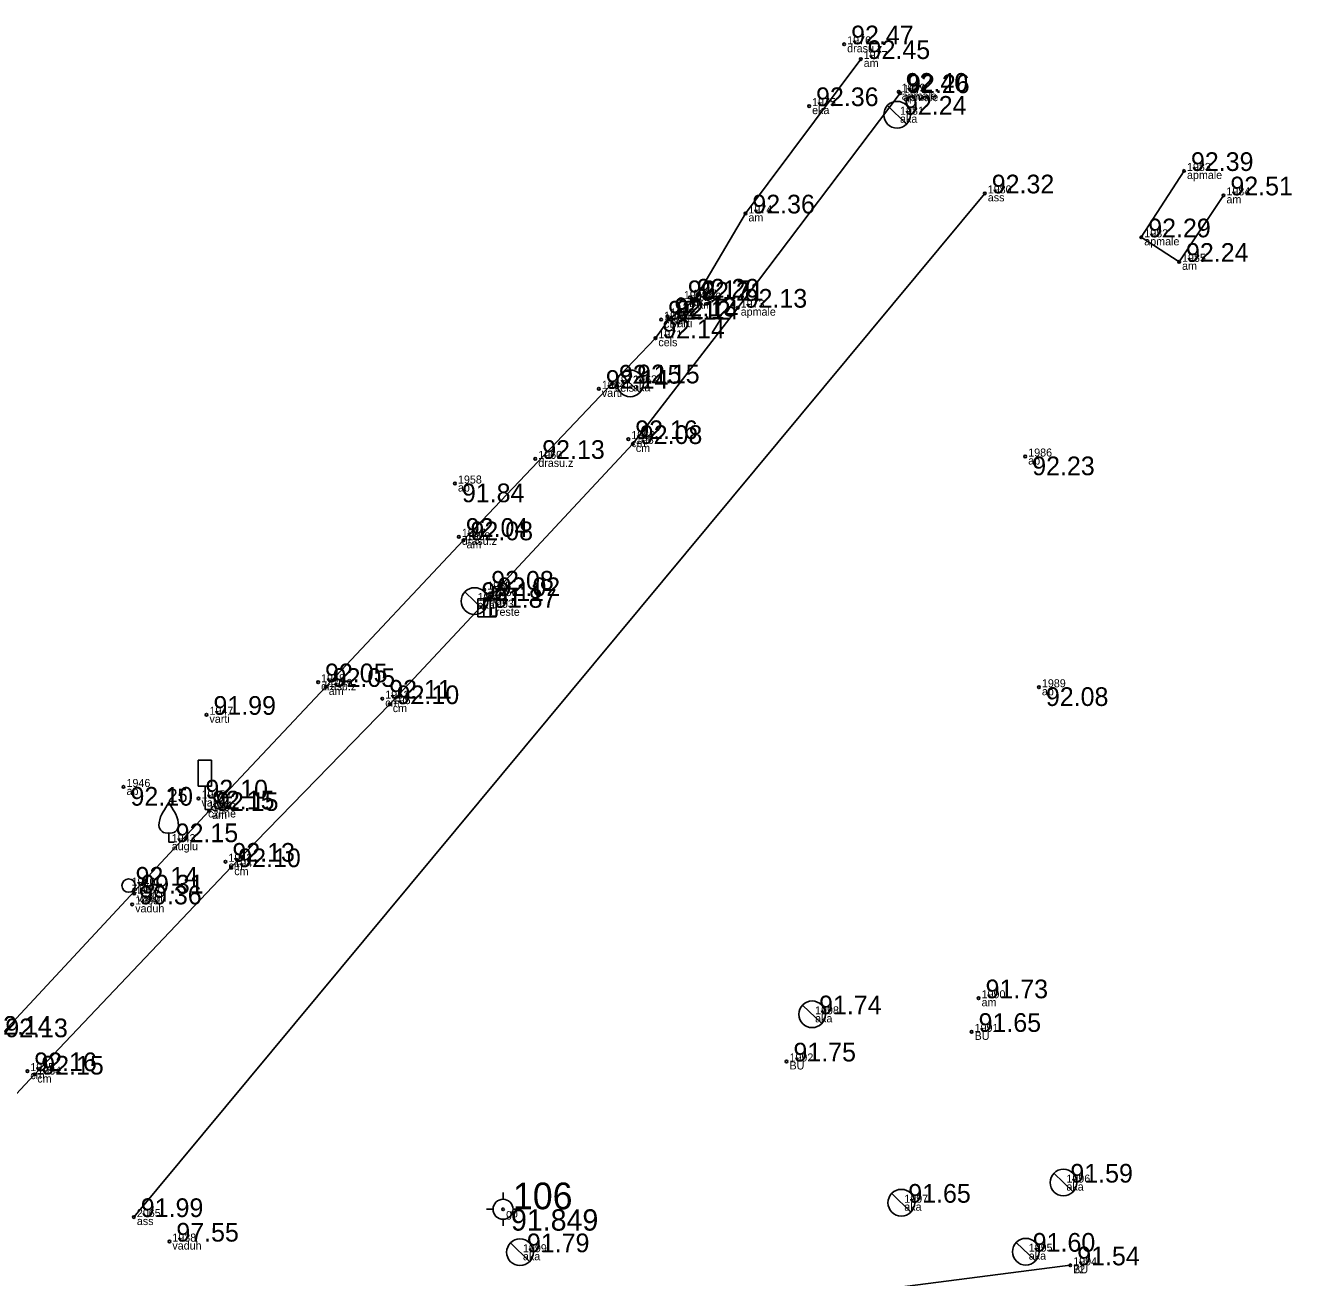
# Model space of a CAD drawing. Extents: x 614911 to 615803, y 262110 to 264311.
# Drawn here: x 615755.92 to 615803.38, y 263539.24 to 263586.14 of the extents above; entities that cross this region are included whole.
import ezdxf

# ---------------------------------------------------------------- set-up
doc = ezdxf.new("R2010")
doc.units = 0
for name, color, linetype in [('Level 1', 7, 'Continuous'), ('Level 12', 7, 'Continuous'), ('Level 16', 7, 'Continuous'), ('Level 18', 7, 'Continuous'), ('Level 19', 7, 'Continuous'), ('Level 37', 7, 'Continuous'), ('Level 48', 7, 'Continuous'), ('Level 53', 7, 'Continuous'), ('Level 54', 7, 'Continuous'), ('Level 57', 7, 'Continuous'), ('Level 58', 7, 'Continuous')]:
    doc.layers.add(name, color=color, linetype=linetype)

msp = doc.modelspace()

# ---------------------------------------------------------------- linework, layer by layer
at = {"layer": 'Level 1'}
for p, q in [((615761.297, 263555.9), (615761.297, 263555.548)), ((615761.297, 263555.548), (615761.497, 263555.548))]:
    msp.add_line(p, q, dxfattribs=at)
for centre, radius, start, end in [((615773.922, 263549.152), 14.88, 148.4844, 149.9901), ((615760.88, 263557.186), 0.439, 324.3837, 341.712), ((615761.714, 263557.186), 0.439, 198.288, 215.6163), ((615748.672, 263549.152), 14.88, 30.0099, 31.5156), ((615761.821, 263556.173), 0.89, 151.757, 179.9138), ((615760.773, 263556.173), 0.89, 0.0862, 28.243), ((615761.221, 263556.179), 0.29, 181.0782, 285.2823), ((615761.373, 263556.179), 0.29, 254.7177, 358.9218)]:
    msp.add_arc(centre, radius, start, end, dxfattribs=at)
at = {"layer": 'Level 12'}
for p, q in [((615788.232, 263583.144), (615788.95, 263582.448)), ((615778.23, 263573.082), (615778.948, 263572.386)), ((615772.399, 263564.928), (615773.117, 263564.232)), ((615785.049, 263549.448), (615785.767, 263548.752)), ((615794.467, 263543.145), (615795.185, 263542.449)), ((615788.392, 263542.391), (615789.11, 263541.695)), ((615774.101, 263540.536), (615774.819, 263539.84)), ((615793.056, 263540.556), (615793.774, 263539.86))]:
    msp.add_line(p, q, dxfattribs=at)
for centre in [(615788.591, 263582.796), (615778.589, 263572.734), (615772.758, 263564.58), (615785.408, 263549.1), (615794.826, 263542.797), (615788.751, 263542.043), (615774.46, 263540.188), (615793.415, 263540.208)]:
    msp.add_circle(centre, 0.5, dxfattribs=at)
at = {"layer": 'Level 16'}
for p, q in [((615762.904, 263558.62), (615762.404, 263558.62)), ((615762.404, 263557.651), (615762.404, 263558.62)), ((615762.904, 263557.651), (615762.904, 263558.62)), ((615762.904, 263557.651), (615762.404, 263557.651)), ((615762.658, 263557.651), (615762.658, 263556.773)), ((615762.658, 263556.773), (615762.973, 263556.773))]:
    msp.add_line(p, q, dxfattribs=at)
at = {"layer": 'Level 18'}
msp.add_circle((615759.794, 263553.919), 0.25, dxfattribs=at)
at = {"layer": 'Level 19'}
for p, q in [((615773.825, 263542.172), (615773.825, 263542.422)), ((615773.2, 263541.797), (615773.45, 263541.797)), ((615774.2, 263541.797), (615774.45, 263541.797)), ((615773.825, 263541.172), (615773.825, 263541.422))]:
    msp.add_line(p, q, dxfattribs=at)
for radius in [0.375, 0.05]:
    msp.add_circle((615773.825, 263541.797), radius, dxfattribs=at)
at = {"layer": 'Level 37'}
for points in [[(615787.229, 263584.883), (615782.908, 263579.099), (615780.991, 263575.833), (615780.048, 263575.138), (615779.534, 263574.424), (615777.908, 263572.723), (615772.346, 263566.856), (615767.18, 263561.364), (615762.809, 263556.719), (615754.912, 263548.241), (615748.93, 263542.698)], [(615748.501, 263540.3), (615752.458, 263542.769), (615756.26, 263546.844), (615763.642, 263554.612), (615769.579, 263560.719), (615773.362, 263564.765), (615778.69, 263570.463), (615782.62, 263575.569), (615788.708, 263583.605)], [(615799.345, 263580.69), (615797.744, 263578.204), (615799.159, 263577.287), (615800.822, 263579.776)], [(615759.991, 263541.506), (615791.879, 263579.85)], [(615636.517, 263431.183), (615636.486, 263438.842), (615637.482, 263455.724), (615637.88, 263461.317), (615641.087, 263475.093), (615646.009, 263486.103), (615652.8, 263496.474), (615655.118, 263496.071), (615654.594, 263498.729), (615665.688, 263509.023), (615675.1, 263515.158), (615678.975, 263516.543), (615699.763, 263520.908), (615714.967, 263523.826), (615751.888, 263531.363), (615772.751, 263536.064), (615784.721, 263538.367), (615795.082, 263539.698)]]:
    msp.add_lwpolyline(points, dxfattribs=at)
at = {"layer": 'Level 48'}
for p, q in [((615773.111, 263564.666), (615773.111, 263563.991)), ((615773.336, 263564.666), (615773.336, 263563.991))]:
    msp.add_line(p, q, dxfattribs=at)
msp.add_lwpolyline([(615772.886, 263564.666), (615773.561, 263564.666), (615773.561, 263563.991), (615772.886, 263563.991)], close=True, dxfattribs=at)
at = {"layer": 'Level 57'}
for centre in [(615786.61, 263585.434), (615787.229, 263584.883), (615788.652, 263583.657), (615788.708, 263583.605), (615785.295, 263583.119), (615799.345, 263580.69), (615791.879, 263579.85), (615800.822, 263579.776), (615782.908, 263579.099), (615797.744, 263578.204), (615799.159, 263577.287), (615780.488, 263575.889), (615780.826, 263575.948), (615780.991, 263575.833), (615779.749, 263575.121), (615779.989, 263575.241), (615780.048, 263575.138), (615782.62, 263575.569), (615779.534, 263574.424), (615777.416, 263572.529), (615777.908, 263572.723), (615778.52, 263570.646), (615778.69, 263570.463), (615775.034, 263569.905), (615793.395, 263569.993), (615772.024, 263568.982), (615772.169, 263566.985), (615772.346, 263566.856), (615773.123, 263565.006), (615773.362, 263564.765), (615766.894, 263561.538), (615767.18, 263561.364), (615793.908, 263561.35), (615769.299, 263560.923), (615769.579, 263560.719), (615762.712, 263560.319), (615759.603, 263557.615), (615762.412, 263557.185), (615762.809, 263556.719), (615763.423, 263554.816), (615763.642, 263554.612), (615760.001, 263553.625), (615759.928, 263553.218), (615791.647, 263549.701), (615791.386, 263548.442), (615784.448, 263547.334), (615755.998, 263546.971), (615756.26, 263546.844), (615759.991, 263541.506), (615761.321, 263540.587), (615795.082, 263539.698)]:
    msp.add_circle(centre, 0.05, dxfattribs=at)
at = {"layer": 'Level 58'}
for centre in [(615786.61, 263585.434), (615787.229, 263584.883), (615788.652, 263583.657), (615788.708, 263583.605), (615785.295, 263583.119), (615799.345, 263580.69), (615791.879, 263579.85), (615800.822, 263579.776), (615782.908, 263579.099), (615797.744, 263578.204), (615799.159, 263577.287), (615780.488, 263575.889), (615780.826, 263575.948), (615780.991, 263575.833), (615779.749, 263575.121), (615779.989, 263575.241), (615780.048, 263575.138), (615782.62, 263575.569), (615779.534, 263574.424), (615777.416, 263572.529), (615777.908, 263572.723), (615778.52, 263570.646), (615778.69, 263570.463), (615775.034, 263569.905), (615793.395, 263569.993), (615772.024, 263568.982), (615772.169, 263566.985), (615772.346, 263566.856), (615773.123, 263565.006), (615773.362, 263564.765), (615766.894, 263561.538), (615767.18, 263561.364), (615793.908, 263561.35), (615769.299, 263560.923), (615769.579, 263560.719), (615762.712, 263560.319), (615759.603, 263557.615), (615762.412, 263557.185), (615762.809, 263556.719), (615763.423, 263554.816), (615763.642, 263554.612), (615760.001, 263553.625), (615759.928, 263553.218), (615791.647, 263549.701), (615791.386, 263548.442), (615784.448, 263547.334), (615755.998, 263546.971), (615756.26, 263546.844), (615759.991, 263541.506), (615761.321, 263540.587), (615795.082, 263539.698)]:
    msp.add_circle(centre, 0.05, dxfattribs=at)

# ---------------------------------------------------------------- texts
at = {"layer": 'Level 1'}
msp.add_text(' 25', height=0.5, dxfattribs=at).set_placement((615761.072, 263557.048))
at = {"layer": 'Level 19'}
for s, height, p in [(' 106', 1, (615773.825, 263541.797)), (' 91.849', 0.8, (615773.825, 263540.997))]:
    msp.add_text(s, height=height, dxfattribs=at).set_placement(p)
at = {"layer": 'Level 48'}
msp.add_text(' 91.87', height=0.7, dxfattribs=at).set_placement((615773.224, 263564.328))
at = {"layer": 'Level 53'}
for s, p in [(' drasu.z', (615786.61, 263585.134)), (' am', (615787.229, 263584.583)), (' apmale', (615788.652, 263583.357)), (' apmale', (615788.708, 263583.305)), (' eka', (615785.295, 263582.819)), (' aka', (615788.591, 263582.496)), (' apmale', (615799.345, 263580.39)), (' ass', (615791.879, 263579.55)), (' am', (615800.822, 263579.476)), (' am', (615782.908, 263578.799)), (' apmale', (615797.744, 263577.904)), (' am', (615799.159, 263576.987)), (' cBr', (615780.488, 263575.589)), (' eka', (615780.826, 263575.648)), (' am', (615780.991, 263575.533)), (' cBr', (615779.989, 263574.941)), (' apmale', (615782.62, 263575.269)), (' cBr', (615779.749, 263574.821)), (' varti', (615780.048, 263574.838)), (' cels', (615779.534, 263574.124)), (' varti', (615777.416, 263572.229)), (' cels', (615777.908, 263572.423)), (' aka', (615778.589, 263572.434)), (' cm', (615778.52, 263570.346)), (' cm', (615778.69, 263570.163)), (' drasu.z', (615775.034, 263569.605)), (' ap', (615793.395, 263569.693)), (' ap', (615772.024, 263568.682)), (' drasu.z', (615772.169, 263566.685)), (' am', (615772.346, 263566.556)), (' cm', (615773.123, 263564.706)), (' aka', (615772.758, 263564.28)), (' Lreste', (615773.224, 263564.028)), (' cm', (615773.362, 263564.465)), (' drasu.z', (615766.894, 263561.238)), (' am', (615767.18, 263561.064)), (' ap', (615793.908, 263561.05)), (' cm', (615769.299, 263560.623)), (' cm', (615769.579, 263560.419)), (' varti', (615762.712, 263560.019)), (' ap', (615759.603, 263557.315)), (' varti', (615762.412, 263556.885)), (' czime', (615762.658, 263556.473)), (' am', (615762.809, 263556.419)), (' auglu', (615761.297, 263555.248)), (' cm', (615763.423, 263554.516)), (' cm', (615763.642, 263554.312)), (' elst', (615759.794, 263553.619)), (' vaduh', (615760.001, 263553.325)), (' vaduh', (615759.928, 263552.918)), (' am', (615791.647, 263549.401)), (' aka', (615785.408, 263548.8)), (' BU', (615791.386, 263548.142)), (' BU', (615784.448, 263547.034)), (' cm', (615755.998, 263546.671)), (' cm', (615756.26, 263546.544)), (' aka', (615794.826, 263542.497)), (' aka', (615788.751, 263541.743)), (' gp', (615773.825, 263541.497)), (' ass', (615759.991, 263541.206)), (' vaduh', (615761.321, 263540.287)), (' aka', (615774.46, 263539.888)), (' aka', (615793.415, 263539.908)), (' 72', (615795.082, 263539.398)), (' BU', (615795.082, 263539.398))]:
    msp.add_text(s, height=0.3, dxfattribs=at).set_placement(p)
at = {"layer": 'Level 54'}
for s, p in [(' 1976', (615786.61, 263585.434)), (' 1977', (615787.229, 263584.883)), (' 1979', (615788.652, 263583.657)), (' 1978', (615788.708, 263583.605)), (' 1975', (615785.295, 263583.119)), (' 1981', (615788.591, 263582.796)), (' 1983', (615799.345, 263580.69)), (' 1980', (615791.879, 263579.85)), (' 1984', (615800.822, 263579.776)), (' 1974', (615782.908, 263579.099)), (' 1982', (615797.744, 263578.204)), (' 1985', (615799.159, 263577.287)), (' 1968', (615780.488, 263575.889)), (' 1967', (615780.826, 263575.948)), (' 1966', (615780.991, 263575.833)), (' 1973', (615782.62, 263575.569)), (' 1970', (615779.749, 263575.121)), (' 1969', (615779.989, 263575.241)), (' 1965', (615780.048, 263575.138)), (' 1971', (615779.534, 263574.424)), (' 1964', (615777.416, 263572.529)), (' 1972', (615777.908, 263572.723)), (' 1963', (615778.589, 263572.734)), (' 1962', (615778.52, 263570.646)), (' 1961', (615778.69, 263570.463)), (' 1960', (615775.034, 263569.905)), (' 1986', (615793.395, 263569.993)), (' 1958', (615772.024, 263568.982)), (' 1957', (615772.169, 263566.985)), (' 1959', (615772.346, 263566.856)), (' 1955', (615773.123, 263565.006)), (' 1954', (615772.758, 263564.58)), (' 1956', (615773.362, 263564.765)), (' 1953', (615773.224, 263564.328)), (' 1948', (615766.894, 263561.538)), (' 1949', (615767.18, 263561.364)), (' 1989', (615793.908, 263561.35)), (' 1951', (615769.299, 263560.923)), (' 1952', (615769.579, 263560.719)), (' 1947', (615762.712, 263560.319)), (' 1946', (615759.603, 263557.615)), (' 1945', (615762.412, 263557.185)), (' 1944', (615762.658, 263556.773)), (' 1950', (615762.809, 263556.719)), (' 1943', (615761.297, 263555.548)), (' 1942', (615763.423, 263554.816)), (' 1941', (615763.642, 263554.612)), (' 1940', (615759.794, 263553.919)), (' 1987', (615760.001, 263553.625)), (' 1988', (615759.928, 263553.218)), (' 1990', (615791.647, 263549.701)), (' 1998', (615785.408, 263549.1)), (' 1991', (615791.386, 263548.442)), (' 1992', (615784.448, 263547.334)), (' 1935', (615755.998, 263546.971)), (' 1934', (615756.26, 263546.844)), (' 1996', (615794.826, 263542.797)), (' 1997', (615788.751, 263542.043)), (' 2065', (615759.991, 263541.506)), (' 1938', (615761.321, 263540.587)), (' 1999', (615774.46, 263540.188)), (' 1995', (615793.415, 263540.208)), (' 1994', (615795.082, 263539.698))]:
    msp.add_text(s, height=0.3, dxfattribs=at).set_placement(p)
at = {"layer": 'Level 58'}
for s, p in [(' 92.47', (615786.61, 263585.434)), (' 92.45', (615787.229, 263584.883)), (' 92.40', (615788.652, 263583.657)), (' 92.26', (615788.708, 263583.605)), (' 92.36', (615785.295, 263583.119)), (' 92.24', (615788.591, 263582.796)), (' 92.39', (615799.345, 263580.69)), (' 92.32', (615791.879, 263579.85)), (' 92.51', (615800.822, 263579.776)), (' 92.36', (615782.908, 263579.099)), (' 92.29', (615797.744, 263578.204)), (' 92.24', (615799.159, 263577.287)), (' 92.17', (615780.488, 263575.889)), (' 92.20', (615780.826, 263575.948)), (' 92.21', (615780.991, 263575.833)), (' 92.13', (615782.62, 263575.569)), (' 92.12', (615779.749, 263575.121)), (' 92.13', (615779.989, 263575.241)), (' 92.14', (615780.048, 263575.138)), (' 92.14', (615779.534, 263574.424)), (' 92.15', (615777.908, 263572.723)), (' 92.15', (615778.589, 263572.734)), (' 92.14', (615777.416, 263572.529)), (' 92.16', (615778.52, 263570.646)), (' 92.08', (615778.69, 263570.463)), (' 92.13', (615775.034, 263569.905)), (' 92.23', (615793.395, 263569.293)), (' 91.84', (615772.024, 263568.282)), (' 92.04', (615772.169, 263566.985)), (' 92.08', (615772.346, 263566.856)), (' 92.08', (615773.123, 263565.006)), (' 92.11', (615772.758, 263564.58)), (' 92.02', (615773.362, 263564.765)), (' 92.05', (615766.894, 263561.538)), (' 92.05', (615767.18, 263561.364)), (' 92.11', (615769.299, 263560.923)), (' 92.10', (615769.579, 263560.719)), (' 91.99', (615762.712, 263560.319)), (' 92.08', (615793.908, 263560.65)), (' 92.10', (615759.603, 263556.915)), (' 92.10', (615762.412, 263557.185)), (' 92.15', (615762.658, 263556.773)), (' 92.15', (615762.809, 263556.719)), (' 92.15', (615761.297, 263555.548)), (' 92.13', (615763.423, 263554.816)), (' 92.10', (615763.642, 263554.612)), (' 92.14', (615759.794, 263553.919)), (' 99.31', (615760.001, 263553.625)), (' 99.36', (615759.928, 263553.218)), (' 91.73', (615791.647, 263549.701)), (' 91.74', (615785.408, 263549.1)), (' 91.65', (615791.386, 263548.442)), (' 92.14', (615754.308, 263548.334)), (' 92.13', (615754.912, 263548.241)), (' 92.16', (615755.998, 263546.971)), (' 91.75', (615784.448, 263547.334)), (' 92.15', (615756.26, 263546.844)), (' 91.59', (615794.826, 263542.797)), (' 91.65', (615788.751, 263542.043)), (' 91.99', (615759.991, 263541.506)), (' 97.55', (615761.321, 263540.587)), (' 91.79', (615774.46, 263540.188)), (' 91.60', (615793.415, 263540.208)), (' 91.54', (615795.082, 263539.698))]:
    msp.add_text(s, height=0.7, dxfattribs=at).set_placement(p)

doc.saveas('drawing.dxf')
